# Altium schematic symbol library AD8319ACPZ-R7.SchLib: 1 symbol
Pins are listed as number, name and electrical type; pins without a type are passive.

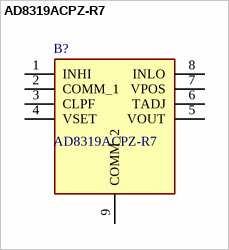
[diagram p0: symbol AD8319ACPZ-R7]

## AD8319ACPZ-R7
designator B?
ANALOG DEVICES - AD8319ACPZ-R7 - Logarithmic Amplifier, 1 Amplifier, 45 dB, 20 ns, LFCSP, 8 Pins; Geometry.Height: 0.8mm
footprint SON50P200X300X80-9N-D
pins: 1 INHI, 2 COMM_1, 3 CLPF, 4 VSET, 5 VOUT, 6 TADJ, 7 VPOS (power), 8 INLO, 9 COMM_2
